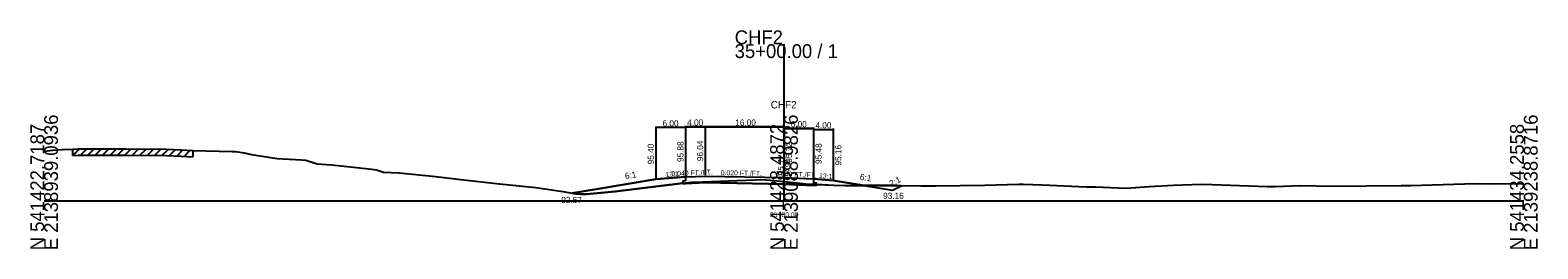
# Model space of a CAD drawing. Extents: x -12831 to 2303, y -10 to 39065.
# Drawn here: x 997.2 to 1302.8, y 9990.3 to 10034.6 of the extents above; entities that cross this region are included whole.
import ezdxf

# ---------------------------------------------------------------- set-up
doc = ezdxf.new("R2010")
doc.units = 0
for name, color, linetype in [('Level 5', 7, 'Continuous'), ('Level 53', 7, 'Continuous'), ('Level 54', 7, 'Continuous'), ('Level 55', 7, 'Continuous'), ('Level 7', 7, 'Continuous'), ('RD_GPK_XS_Cell', 7, 'Continuous'), ('RD_XS_EwShp', 7, 'Continuous'), ('RD_XS_ExGround', 7, 'Continuous'), ('RD_XS_ExPaveRet', 7, 'Continuous'), ('RD_XS_Pave', 7, 'Continuous'), ('RD_XS_TX_Baseline', 7, 'Continuous'), ('RD_XS_TX_Elev_EX', 7, 'Continuous'), ('RD_XS_TX_Elev_PR', 7, 'Continuous'), ('RD_XS_TX_Station', 7, 'Continuous')]:
    doc.layers.add(name, color=color, linetype=linetype)

msp = doc.modelspace()

# ---------------------------------------------------------------- linework, layer by layer
at = {"layer": 'Level 5'}
for p, q in [((1130, 10004.05), (1129.5, 10004.03)), ((1129.5, 10004.03), (1129.5, 10003.53)), ((1129.5, 10003.53), (1130, 10003.55)), ((1130, 10004.88), (1130, 10004.05)), ((1134, 10003.71), (1130, 10003.55)), ((1134, 10003.71), (1130, 10003.55)), ((1130, 10003.55), (1134, 10003.71)), ((1150, 10003.39), (1134, 10003.71)), ((1150, 10003.39), (1134, 10003.71)), ((1134, 10003.71), (1150, 10003.39)), ((1134, 10003.71), (1150, 10003.39)), ((1156, 10003.15), (1150, 10003.39)), ((1150, 10003.39), (1156, 10003.15)), ((1150, 10003.39), (1156, 10003.15)), ((1156, 10004.48), (1156, 10003.65)), ((1156, 10003.65), (1156.5, 10003.63)), ((1156.5, 10003.13), (1156, 10003.15)), ((1156.5, 10003.63), (1156.5, 10003.13))]:
    msp.add_line(p, q, dxfattribs=at)
at = {"layer": 'Level 54'}
for p, q in [((1124, 10015.03), (1124, 10004.6)), ((1130, 10014.83), (1124, 10014.83)), ((1130, 10015.19), (1130, 10005.08)), ((1130, 10015.19), (1130, 10005.08)), ((1130, 10015.19), (1130, 10005.08)), ((1130, 10015.03), (1130, 10005.08)), ((1130, 10014.99), (1134, 10014.99)), ((1130, 10014.99), (1134, 10014.99)), ((1134, 10014.99), (1130, 10014.99)), ((1134, 10015.19), (1134, 10005.24)), ((1134, 10015.19), (1134, 10005.24)), ((1134, 10015.19), (1134, 10005.24)), ((1134, 10015.19), (1134, 10005.24)), ((1134, 10015.19), (1134, 10005.24)), ((1134, 10015.19), (1134, 10005.24)), ((1134, 10015.19), (1134, 10005.24)), ((1134, 10014.99), (1150, 10014.99)), ((1134, 10014.99), (1150, 10014.99)), ((1150, 10014.99), (1134, 10014.99)), ((1150, 10014.99), (1134, 10014.99)), ((1150, 10015.19), (1150, 10004.92)), ((1150, 10015.19), (1150, 10004.92)), ((1150, 10015.19), (1150, 10004.92)), ((1150, 10015.19), (1150, 10004.92)), ((1150, 10014.87), (1150, 10004.92)), ((1150, 10014.87), (1150, 10004.92)), ((1150, 10014.87), (1150, 10004.92)), ((1150, 10014.67), (1156, 10014.67)), ((1156, 10014.67), (1150, 10014.67)), ((1156, 10014.67), (1150, 10014.67)), ((1156, 10014.87), (1156, 10004.68)), ((1156, 10014.87), (1156, 10004.68)), ((1156, 10014.87), (1156, 10004.68)), ((1156, 10014.63), (1156, 10004.68)), ((1156, 10014.43), (1160, 10014.43)), ((1160, 10014.63), (1160, 10004.36))]:
    msp.add_line(p, q, dxfattribs=at)
at = {"layer": 'Level 7'}
for p, q in [((1112, 10002.4), (1107, 10001.57)), ((1124, 10004.4), (1112, 10002.4)), ((1130, 10004.88), (1124, 10004.4)), ((1156, 10004.48), (1160, 10004.16)), ((1160, 10004.16), (1172, 10002.16)), ((1172, 10002.16), (1173.83, 10003.08))]:
    msp.add_line(p, q, dxfattribs=at)
at = {"layer": 'RD_GPK_XS_Cell'}
for p, q in [((1150, 10000), (1150, 10031.72)), ((1000, 10000), (1150, 10000)), ((1150, 10000), (1300, 10000))]:
    msp.add_line(p, q, dxfattribs=at)
at = {"layer": 'RD_XS_EwShp'}
for points in [[(1130, 10004.88), (1130, 10004.05), (1129.5, 10004.03), (1129.5, 10003.58), (1115.79, 10001.92), (1109.98, 10001.35), (1108.65, 10001.4), (1107.81, 10001.42), (1107, 10001.57), (1112, 10002.4), (1124, 10004.4)], [(1134, 10003.71), (1130, 10003.55), (1129.5, 10003.53), (1129.5, 10003.58), (1131.17, 10003.78), (1131.65, 10003.8), (1144.12, 10004.26), (1145.29, 10004.31), (1147.2, 10004.22), (1150, 10003.93), (1155.13, 10003.41), (1156.5, 10003.36), (1156.5, 10003.13), (1156, 10003.15), (1150, 10003.39)], [(1156, 10004.48), (1156, 10003.65), (1156.5, 10003.63), (1156.5, 10003.36), (1160.11, 10003.22), (1162.33, 10003.12), (1165.25, 10003.13), (1166.22, 10003.12), (1160, 10004.16)], [(1172, 10002.16), (1173.83, 10003.08), (1172.9, 10003.09), (1166.22, 10003.12)]]:
    msp.add_lwpolyline(points, close=True, dxfattribs=at)
at = {"layer": 'RD_XS_ExGround'}
for p, q in [((1000, 10010.1), (1001.74, 10010.25)), ((1001.74, 10010.25), (1003.65, 10010.41)), ((1003.65, 10010.41), (1005.83, 10010.49)), ((1005.83, 10010.49), (1006.92, 10010.53)), ((1006.92, 10010.53), (1008.71, 10010.57)), ((1008.71, 10010.57), (1016.58, 10010.53)), ((1016.58, 10010.53), (1024.76, 10010.46)), ((1024.76, 10010.46), (1027.75, 10010.34)), ((1027.75, 10010.34), (1030.16, 10010.23)), ((1030.16, 10010.23), (1038.09, 10010.01)), ((1038.09, 10010.01), (1038.84, 10009.98)), ((1038.84, 10009.98), (1040.57, 10009.76)), ((1040.57, 10009.76), (1042.06, 10009.42)), ((1042.06, 10009.42), (1047.25, 10008.59)), ((1047.25, 10008.59), (1052.17, 10008.3)), ((1052.17, 10008.3), (1053.07, 10008.25)), ((1053.07, 10008.25), (1055.38, 10007.48)), ((1055.38, 10007.48), (1058.31, 10007.3)), ((1058.31, 10007.3), (1060.24, 10007.11)), ((1060.24, 10007.11), (1066.45, 10006.43)), ((1066.45, 10006.43), (1067.36, 10006.3)), ((1067.36, 10006.3), (1068.8, 10005.82)), ((1068.8, 10005.82), (1071.99, 10005.66)), ((1071.99, 10005.66), (1079.4, 10004.96)), ((1079.4, 10004.96), (1083.85, 10004.37)), ((1083.85, 10004.37), (1092.34, 10003.46)), ((1092.34, 10003.46), (1099.66, 10002.73)), ((1099.66, 10002.73), (1105.16, 10001.9)), ((1105.16, 10001.9), (1107.81, 10001.42)), ((1109.98, 10001.35), (1115.79, 10001.92)), ((1115.79, 10001.92), (1131.17, 10003.78)), ((1131.17, 10003.78), (1131.65, 10003.8)), ((1131.65, 10003.8), (1144.12, 10004.26)), ((1144.12, 10004.26), (1145.29, 10004.31)), ((1145.29, 10004.31), (1147.2, 10004.22)), ((1147.2, 10004.22), (1150, 10003.93)), ((1150, 10003.93), (1155.13, 10003.41)), ((1155.13, 10003.41), (1160.11, 10003.22)), ((1160.11, 10003.22), (1162.33, 10003.12)), ((1162.33, 10003.12), (1165.25, 10003.13)), ((1165.25, 10003.13), (1172.9, 10003.09)), ((1172.9, 10003.09), (1177.74, 10003.04)), ((1177.74, 10003.04), (1180.73, 10003.07)), ((1180.73, 10003.07), (1190.74, 10003.18)), ((1190.74, 10003.18), (1197.62, 10003.38)), ((1197.62, 10003.38), (1198.1, 10003.39)), ((1198.1, 10003.39), (1198.46, 10003.36)), ((1198.46, 10003.36), (1202.4, 10003.23)), ((1202.4, 10003.23), (1211.25, 10002.87)), ((1211.25, 10002.87), (1212.07, 10002.88)), ((1212.07, 10002.88), (1213.17, 10002.83)), ((1213.17, 10002.83), (1219.37, 10002.6)), ((1219.37, 10002.6), (1224.03, 10002.91)), ((1224.03, 10002.91), (1228.95, 10003.22)), ((1228.95, 10003.22), (1234.63, 10003.42)), ((1234.63, 10003.42), (1236.81, 10003.35)), ((1236.81, 10003.35), (1247.93, 10002.89)), ((1247.93, 10002.89), (1249.6, 10002.9)), ((1249.6, 10002.9), (1254.7, 10003.12)), ((1254.7, 10003.12), (1261.03, 10002.96)), ((1261.03, 10002.96), (1275.16, 10003.09)), ((1275.16, 10003.09), (1276.05, 10003.11)), ((1276.05, 10003.11), (1277.12, 10003.14)), ((1277.12, 10003.14), (1287.95, 10003.48)), ((1287.95, 10003.48), (1290.55, 10003.51)), ((1290.55, 10003.51), (1293.85, 10003.49)), ((1293.85, 10003.49), (1300, 10003.54)), ((1107.81, 10001.42), (1108.65, 10001.4)), ((1108.65, 10001.4), (1109.98, 10001.35))]:
    msp.add_line(p, q, dxfattribs=at)
at = {"layer": 'RD_XS_ExPaveRet'}
for p, q in [((1005.83, 10009.19), (1007.18, 10010.54)), ((1005.83, 10009.19), (1005.83, 10010.49)), ((1005.83, 10009.19), (1006.92, 10009.23)), ((1006.92, 10009.23), (1008.71, 10009.27)), ((1007.34, 10009.24), (1008.67, 10010.57)), ((1008.71, 10009.27), (1016.58, 10009.23)), ((1008.84, 10009.27), (1010.13, 10010.56)), ((1010.34, 10009.26), (1011.64, 10010.56)), ((1011.84, 10009.26), (1013.14, 10010.55)), ((1013.35, 10009.25), (1014.64, 10010.54)), ((1014.85, 10009.24), (1016.15, 10010.53)), ((1016.35, 10009.23), (1017.64, 10010.52)), ((1016.58, 10009.23), (1024.76, 10009.16)), ((1017.86, 10009.22), (1019.15, 10010.51)), ((1019.36, 10009.21), (1020.65, 10010.5)), ((1020.86, 10009.19), (1022.15, 10010.48)), ((1022.36, 10009.18), (1023.65, 10010.47)), ((1023.87, 10009.17), (1025.15, 10010.44)), ((1024.76, 10009.16), (1027.75, 10009.04)), ((1025.37, 10009.13), (1026.62, 10010.39)), ((1026.87, 10009.08), (1028.12, 10010.33)), ((1027.75, 10009.04), (1030.16, 10008.93)), ((1028.38, 10009.01), (1029.62, 10010.26)), ((1030.16, 10010.23), (1030.16, 10008.93))]:
    msp.add_line(p, q, dxfattribs=at)
at = {"layer": 'RD_XS_Pave'}
for p, q in [((1130, 10004.88), (1134, 10005.04)), ((1134, 10005.04), (1150, 10004.72)), ((1150, 10004.72), (1156, 10004.48))]:
    msp.add_line(p, q, dxfattribs=at)

# ---------------------------------------------------------------- texts
at = {"layer": 'Level 53'}
for s, rotation, p in [('95.40', 90, (1123.62, 10007.4)), ('95.88', 90, (1129.62, 10007.88)), ('96.04', 90, (1133.62, 10008.04)), ('96.04', 90, (1133.62, 10008.04)), ('95.72', 90, (1151.63, 10007.72)), ('95.72', 90, (1151.63, 10007.72)), ('95.48', 90, (1157.63, 10007.48)), ('95.16', 90, (1161.63, 10007.16)), ('6:1', 9.4623, (1117.84, 10004.39)), ('6:1', 350.5377, (1165.3, 10004.29))]:
    msp.add_text(s, height=1.25, rotation=rotation, dxfattribs=at).set_placement(p)
for s, p in [('92.57', (1104.84, 9999.57)), ('93.16', (1170.1, 10000.41))]:
    msp.add_text(s, height=1.25, dxfattribs=at).set_placement(p)
at = {"layer": 'Level 54'}
for s, p in [('6.00', (1125.37, 10015.08)), ('4.00', (1130.37, 10015.24)), ('4.00', (1130.37, 10015.24)), ('4.00', (1130.37, 10015.24)), ('16.00', (1140.12, 10015.24)), ('16.00', (1140.12, 10015.24)), ('16.00', (1140.12, 10015.24)), ('16.00', (1140.12, 10015.24)), ('6.00', (1151.37, 10014.92)), ('6.00', (1151.37, 10014.92)), ('6.00', (1151.37, 10014.92)), ('4.00', (1156.37, 10014.68))]:
    msp.add_text(s, height=1.25, dxfattribs=at).set_placement(p)
at = {"layer": 'Level 55'}
for s, height, rotation, p in [('13:1', 1, 4.5739, (1126.03, 10004.81)), ('0.040 FT./FT.', 1, 2.2906, (1127.22, 10005.02)), ('0.040 FT./FT.', 1, 2.2906, (1127.22, 10005.02)), ('0.040 FT./FT.', 1, 2.2906, (1127.22, 10005.02)), ('0.020 FT./FT.', 1, 358.8542, (1137.18, 10005.23)), ('0.020 FT./FT.', 1, 358.8542, (1137.18, 10005.23)), ('0.020 FT./FT.', 1, 358.8542, (1137.18, 10005.23)), ('0.020 FT./FT.', 1, 358.8542, (1137.18, 10005.23)), ('0.040 FT./FT.', 1, 357.7094, (1148.24, 10005.04)), ('0.040 FT./FT.', 1, 357.7094, (1148.24, 10005.04)), ('0.040 FT./FT.', 1, 357.7094, (1148.24, 10005.04)), ('13:1', 1, 355.4261, (1157.07, 10004.65)), ('2:1', 1.25, 26.5651, (1171.74, 10002.87))]:
    msp.add_text(s, height=height, rotation=rotation, dxfattribs=at).set_placement(p)
at = {"layer": 'RD_GPK_XS_Cell'}
for s, p in [('CHF2', (1140, 10031.72)), ('35+00.00 / 1', (1140, 10028.92))]:
    msp.add_text(s, height=2.8, dxfattribs=at).set_placement(p)
for s, p in [('E 2138939.0936', (1002.8, 9990)), ('E 2139088.9826', (1152.8, 9990)), ('E 2139238.8716', (1302.8, 9990)), ('N 541422.7187', (1000, 9990)), ('N 541428.4872', (1150, 9990)), ('N 541434.2558', (1300, 9990))]:
    msp.add_text(s, height=2.8, rotation=90, dxfattribs=at).set_placement(p)
at = {"layer": 'RD_XS_TX_Baseline'}
msp.add_text('CHF2', height=1.5, dxfattribs=at).set_placement((1147.31, 10018.72))
at = {"layer": 'RD_XS_TX_Elev_EX'}
msp.add_text('94.93', height=1, rotation=90, dxfattribs=at).set_placement((1151.25, 10004.93))
at = {"layer": 'RD_XS_TX_Elev_PR'}
msp.add_text(' 95.72', height=1.25, rotation=90, dxfattribs=at).set_placement((1150, 10004.72))
at = {"layer": 'RD_XS_TX_Station'}
msp.add_text('35+00.00', height=1, dxfattribs=at).set_placement((1147.14, 9996.72))

doc.saveas('drawing.dxf')
